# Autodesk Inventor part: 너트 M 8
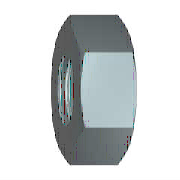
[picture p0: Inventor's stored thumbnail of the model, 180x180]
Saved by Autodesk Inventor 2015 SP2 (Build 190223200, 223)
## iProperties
IsCustomPart: 1
Created: 2012-02
Part Number: 너트 M 8
Material: 강철, 연강
Description: 6각 너트 및 6각 가는 너트
Document SubType Name: Modeling
Standard: KS B 1012
Designer: mduedu
Standards Organization: KS
Language: ko-KR
Size Designation: M 8
Categories: <MemberInstance><Categories><Category DisplayName="조임쇠" InternalName="e4da775c-781d-43d5-af7c-5136215cf5a6" Mnemonic="FSTN"><Category DisplayName="너트" InternalN
Density: 1 g/cm^3
Appearance: 강철
Author: mduedu
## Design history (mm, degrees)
sketch "스케치1"
  geometry: L1 (-7.506, 0)-(-3.753, 6.5); L2 (-3.753, 6.5)-(3.753, 6.5); L3 (3.753, 6.5)-(7.506, 0); L4 (7.506, 0)-(3.753, -6.5); L5 (3.753, -6.5)-(-3.753, -6.5); L6 (-3.753, -6.5)-(-7.506, 0); 2 further points
  constraints: 12 end point, 1 coincident, 1 horizontal, 11 other
  dimensions: "d0" = 15.01111 distance of L3.end L1.start (= 1.1547 x SW)
extrude "본체" new body sketch "스케치1" distance "d1" = 5 (= KOH); taper "d2" = 0 deg
sketch "스케치2"
  geometry: L1 (0, 3.753)-(0, 7.506) reference; L2 (0, 7.506)-(5, 7.506) reference; L3 (5, 3.753)-(5, 7.506) reference; L4 (-1, 0)-(6, 0) reference; L5 (0.581, 7.506)-(0, 6.5); L6 (4.419, 7.506)-(5, 6.5)
  constraints: 4 end point, 4 point on line
  dimensions: "d3" = 30 deg angle of L1 L5 (= ANG1); "d4" = 30 deg angle of L3 L6 (= ANG2); "d5" = 13 diameter of L5.end L4 (= SW0); "d6" = 13 diameter of L6.end L4 (= SW01)
revolve "모따기1" sketch "스케치2" stored, may be unused: angle "d7" = 90 deg
sketch "스케치3"
  geometry: A1 r 6.5 centre (0, 0) between (-3.25, -5.629) and (3.25, -5.629) reference; 1 further point
  constraints: 1 coincident
hole "스레드" sketch "스케치3" at (0, 0) diameter "d25" = 6.647; stored, may be unused: countersink angle "d29" = 82 deg, drill point angle "d31" = 118 deg; dims "d26" = 6, "d27" = 4, "d28" = 2, "d30" = 8
workaxis "Work Axis1"
workplane "Work Plane1"
body "Solid1"
chamfer "모따기2" distance "d8" = 0.67658 (= -0.5 x GD1 + 0.5 x NND); stored, may be unused: angle "d9" = 30 deg, second distance "d40" = 0.67658 (= -0.5 x GD1 + 0.5 x NND)
chamfer "모따기3" distance "d10" = 0.67658 (= -0.5 x GD1 + 0.5 x NND); stored, may be unused: angle "d11" = 30 deg, second distance "d41" = 0.67658 (= -0.5 x GD1 + 0.5 x NND)
other parameters: "ANG1" = 30 deg [user parameter; used in 1 equation term], "ANG2" = 30 deg [user parameter; used in 1 equation term], "NND" = 8 [user parameter; used in 4 equation terms], "KOH" = 5 [user parameter; used in 1 equation term], "SW" = 13 [user parameter; used in 4 equation terms], "SW0" = 13 (= SW) [user parameter; used in 1 equation term], "SW01" = 13 (= SW) [user parameter; used in 1 equation term], "GD1" = 6.64684 (computed from THREADDIA, PTC, TOA) [user parameter; used in 4 equation terms], "d13" = 0, "d14" = 0, "d39" = 0, "d42" = 0, "GUL" = 0.67658 (= 0.541266 x PTC) [user parameter], "TPU" = 8 (computed from PTC) [user parameter], "THREADDIA" = 8 [user parameter; used in 1 equation term], "TOA" = 30 deg [user parameter; used in 1 equation term], "PTC" = 1.25 [user parameter; used in 4 equation terms], "E0" = 15.015 (= 1.155 x SW) [user parameter], "GAL" = 0.67658 (= 0.541266 x PTC) [user parameter]
